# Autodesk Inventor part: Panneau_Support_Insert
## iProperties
Created: 2009-01
Part Number: Panneau_Support_Insert
Material: Acier galvanisé
Document SubType Name: Modeling
Designer: claivier
Author: claivier
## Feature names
1. Extrusion1
2. Perçage1 [Hole]
